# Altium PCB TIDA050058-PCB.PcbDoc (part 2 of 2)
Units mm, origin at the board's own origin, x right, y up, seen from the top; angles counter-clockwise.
Board outline 100 x 60.38 mm, 2 copper layers (Top Layer, Bottom Layer), stack 1.575 mm thick; 72 components, 26 nets, 132 pads, 53 vias.
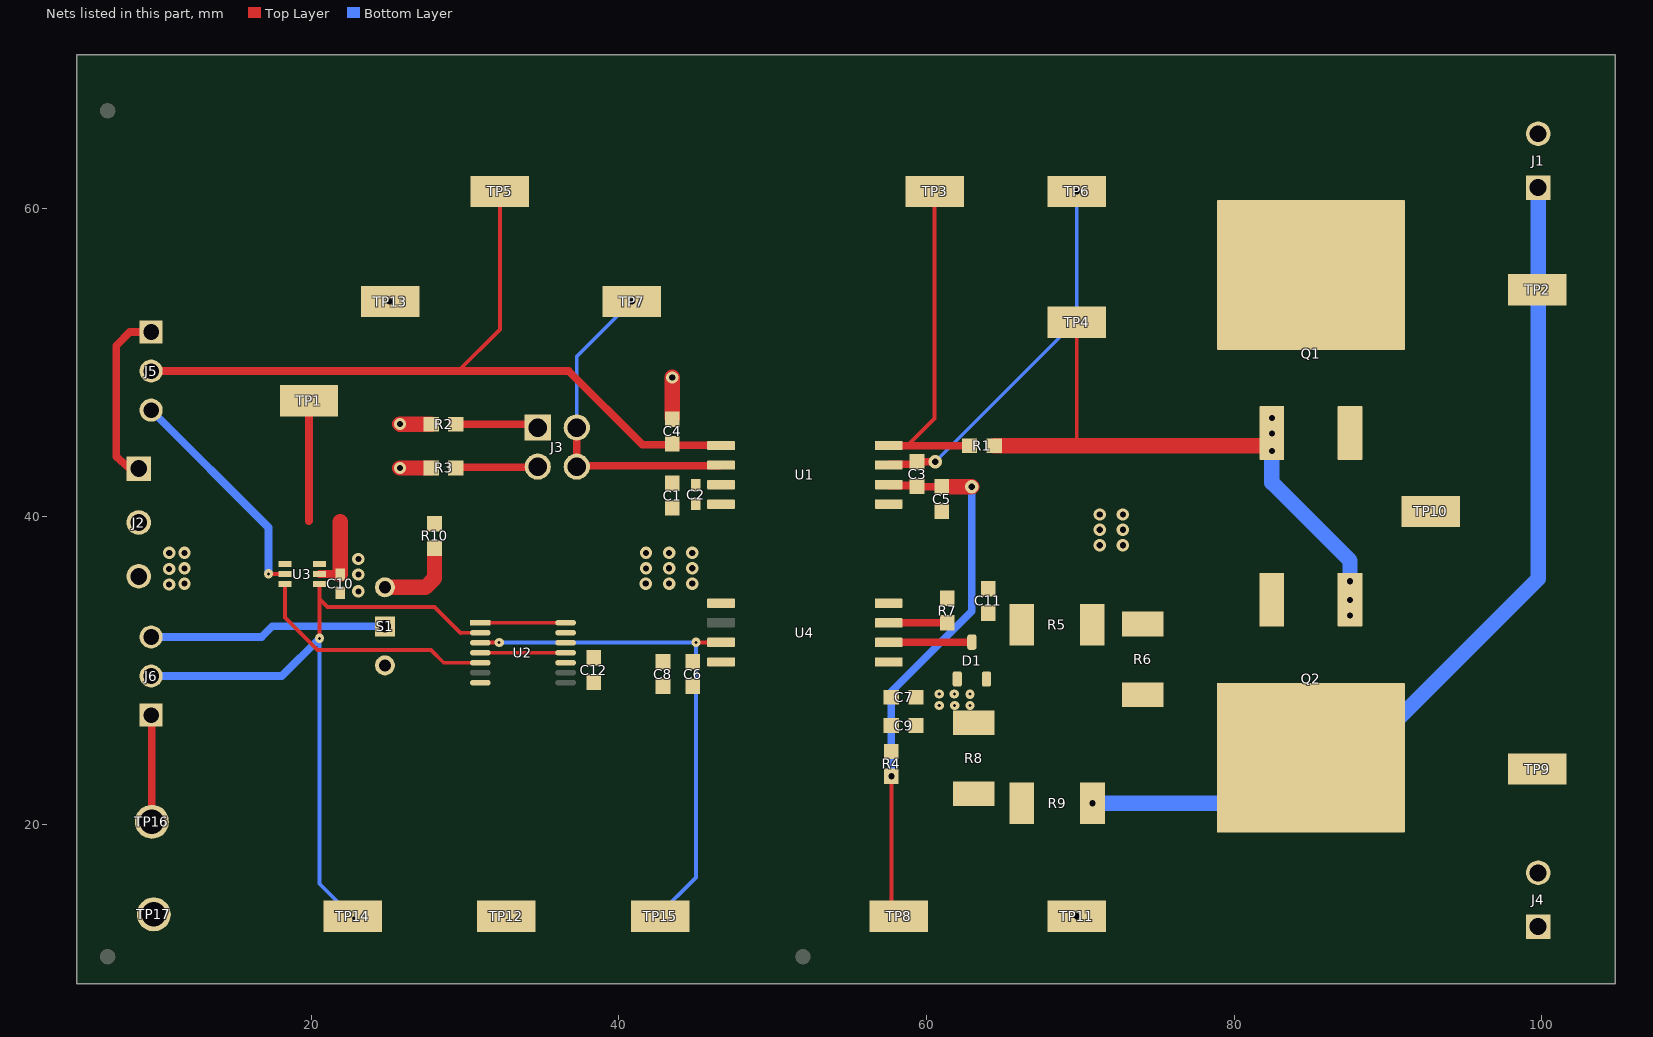
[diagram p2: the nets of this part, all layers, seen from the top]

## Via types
v1: diameter 0.8, hole 0.4, Top Layer to Bottom Layer, tented both sides, 35 vias
v2: diameter 0.61, hole 0.203, Top Layer to Bottom Layer, tented both sides, 12 vias
v3: diameter 0.864, hole 0.406, Top Layer to Bottom Layer, tented both sides, 6 vias

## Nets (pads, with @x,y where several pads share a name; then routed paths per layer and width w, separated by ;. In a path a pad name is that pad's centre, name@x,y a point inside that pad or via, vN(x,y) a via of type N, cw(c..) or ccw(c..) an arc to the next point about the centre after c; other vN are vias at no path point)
EN: C4.1 J5.2 TP5.1 U1.1 | length 51.9
  Top Layer w0.25: 29.568,49.445 32.275,52.152 TP5.1@32.275,61.125
  Top Layer w0.5: J5.2@9.601,49.445 29.568,49.445 36.756,49.445 41.547,44.654 43.49,44.654 43.517,44.627 46.624,44.627 U1.1@46.651,44.6
NetC3_1: C3.1 TP6.1 U1.7 | length 24.5
  Top Layer w0.5: U1.7@57.551,43.33 57.601,43.38 59.226,43.38 C3.1@59.391,43.545 59.394,43.548 60.573,43.548 v3(60.575,43.55)
  Bottom Layer w0.25: v3(60.575,43.55) 69.775,52.75 v3(69.775,61.125)
NetC7_2: C7.2 C9.2 R4.1 U4.1
NetC11_1: C11.1 D1.3 R5.1 U4.2 | length 5.5
  Top Layer w0.5: U4.2@57.551,31.81 62.907,31.81 62.957,31.76 62.957,31.725 D1.3@62.965,31.733
NetJ3_1: J3.1 R2.2 | length 5.4
  Top Layer w0.5: R2.2@29.412,45.995 34.511,45.995 J3.1@34.734,45.773
NetJ3_3: J3.3 R3.2 | length 5.4
  Top Layer w0.5: R3.2@29.412,43.145 29.456,43.189 34.69,43.189 J3.3@34.734,43.233
NetR5_2: R5.2 R6.1
NetR7_2: R7.2 U4.3 | length 3.9
  Top Layer w0.5: U4.3@57.551,33.08 57.554,33.078 61.447,33.078 R7.2@61.45,33.075
NetR8_2: R8.2 R9.1
NetR10_2: R10.2 S1.2 | length 5.4
  Top Layer w1: S1.2@24.8,35.39 27.439,35.39 28.025,35.976 R10.2@28.025,37.925
NetU2_5: U2.5 U3.6 | length 16.1
  Top Layer w0.25: U3.6@18.3,35.6 18.3,33.427 20.423,31.305 27.803,31.305 28.624,30.484 U2.5@31,30.484
OUT2_CLK: TP15.1 U2.3 U4.7 | length 34.5
  Top Layer w0.25: U2.3@31,31.784 31.006,31.791 32.219,31.791 v2(32.225,31.797) ; v2(45.025,31.81) U4.7@46.651,31.81
  Bottom Layer w0.25: v2(32.225,31.797) 32.232,31.803 v2@45.018,31.803 ; v2(42.494,14) 45.013,16.519 45.013,31.798 v2@45.018,31.803 ; v2(45.025,31.81) v2@45.018,31.803
PXFR: J3.2 J3.4 TP7.1 U1.2 | length 21.6
  Top Layer w0.5: J3.2@37.274,45.773 J3.4@37.274,43.233 37.322,43.281 46.603,43.281 U1.2@46.651,43.33
  Bottom Layer w0.25: J3.2@37.274,45.773 37.274,50.393 v3(40.847,53.966)
SEL: J6.2 TP14.1 U2.2 U3.1 | length 46
  Top Layer w0.25: v2(20.55,32.068) 20.55,34.64 ; U3.1@20.55,35.6 20.55,34.64 ; U2.2@31,32.434 30.995,32.43 29.73,32.43 29.725,32.425 28.035,34.115 21.075,34.115 20.55,34.64
  Bottom Layer w0.25: v2(20.55,32.068) 20.55,16.114 v2(22.775,13.889)
  Bottom Layer w0.5: J6.2@9.601,29.62 18.102,29.62 v2(20.55,32.068)
SW1: J1.1 J1.2 Q1.4 R9.2 TP2.1 | length 60.5
  Bottom Layer w1: v3(70.8,21.35) 85.193,21.35 99.775,35.932 J1.1@99.775,61.375
SW2: J4.1 J4.2 Q2.4 R6.2 TP9.1
SWITCH_SEL: J6.3 S1.1 | length 15.5
  Bottom Layer w0.5: J6.3@9.601,32.16 16.791,32.16 17.481,32.85 S1.1@24.8,32.85
USER_EN: J2.1 J5.1 | length 11.7
  Top Layer w0.5: J2.1@8.185,43.142 7.326,43.878 7.326,51.095 8.216,51.985 J5.1@9.601,51.985 ; J2.1@8.26,43.145 J2.1@8.985,43.145
USER_SEL: J6.1 TP16.1 | length 7
  Top Layer w0.5: J6.1@9.601,27.08 9.651,27.03 TP16.1@9.651,20.145
VDDM: C3.2 C5.1 R4.2 TP8.1 U1.6 | length 35.8
  Top Layer w0.25: v3(57.725,23.112) 57.725,14.469 TP8.1@58.194,14
  Top Layer w0.5: U1.6@57.551,42.06 57.601,42.01 59.326,42.01 C3.2@59.391,41.945 59.406,41.93 60.967,41.93 C5.1@60.982,41.916
  Top Layer w1: C5.1@60.982,41.916 62.943,41.916 v3(62.957,41.93)
  Bottom Layer w0.5: v3(57.725,23.112) 57.725,28.59 62.957,33.822 v3(62.957,41.93)
VDDP: C1.1 C2.1 C6.1 C8.1 C10.1 C12.1 J2.2 R10.1 TP1.1 U1.3 U2.1 U2.4 U2.10 U2.11 U2.12 U2.13 U2.14 U3.2 U4.8 | length 23.7
  Top Layer w0.25: U2.4@31,31.134 U2.11@36.55,31.134 ; U2.1@31,33.084 U2.14@36.55,33.084
  Top Layer w0.5: 19.857,39.703 19.864,39.711 TP1.1@19.864,47.516 ; U3.2@20.55,36.25 21.87,36.25 C10.1@21.895,36.225
  Top Layer w1: C10.1@21.895,36.225 21.895,39.643
VDRV: R1.1 TP3.1 U1.8 | length 22.5
  Top Layer w0.25: 58.775,44.6 60.532,46.357 TP3.1@60.532,61.125 ; 59.325,44.6 59.326,44.601
  Top Layer w0.5: U1.8@57.551,44.6 58.775,44.6 59.325,44.6 R1.1@62.801,44.6
VDRV1: Q1.1 Q2.1 R1.2 TP4.1 | length 41.2
  Top Layer w0.25: 69.775,44.6 TP4.1@69.775,52.625 ; 71.584,44.59 71.585,44.591
  Top Layer w1: R1.2@64.401,44.6 64.411,44.59 71.584,44.59 72.509,44.59 82.17,44.59 Q1.1@82.47,44.89
  Bottom Layer w1: v1(82.46,46.39) v1(82.46,45.39) 82.46,42.195 87.54,37.115 v1(87.54,33.561)
  other v1: 87.54,34.572 87.54,35.785 82.46,44.258
VSSP: C1.2 C2.2 C4.2 C6.2 C8.2 C10.2 C12.2 J2.3 R2.1 R3.1 S1.3 TP12.1 TP13.1 TP17.1 U1.4 U2.7 U3.3 U3.4 U4.5 | length 6.7
  Top Layer w1: v1(25.775,43.145) R3.1@27.812,43.145 ; v1(25.775,46) 25.78,45.995 R2.1@27.812,45.995 ; v1(43.476,49.032) 43.49,49.018 C4.2@43.49,46.395
  other v1: 23.075,35.125 10.771,35.575 11.775,35.625 41.76,35.625 43.278,35.625 44.775,35.625 23.075,36.225 10.771,36.575 11.775,36.619 41.775,36.619 43.275,36.625 44.775,36.625 23.075,37.225 10.775,37.625 11.775,37.625 41.775,37.625 43.275,37.625 44.775,37.625 25.097,53.966
VSSS: C5.2 C7.1 C9.1 C11.2 D1.1 D1.2 Q1.3 Q2.3 R7.1 R8.1 TP10.1 TP11.1 U1.5 U4.4
  other v1: 69.775,14 71.275,38.125 72.775,38.125 71.275,39.125 72.775,39.125 71.275,40.125 72.775,40.125
  other v2: 60.84,27.708 61.84,27.708 62.84,27.708 60.84,28.45 61.82,28.45 62.84,28.443
ZCD_EN: J5.3 U3.5 | length 14.9
  Top Layer w0.25: v2(17.233,36.26) 17.238,36.255 18.295,36.255 U3.5@18.3,36.25
  Bottom Layer w0.5: J5.3@9.601,46.905 17.233,39.274 v2(17.233,36.26)
pads on no net: FID1.1 FID2.1 FID3.1 SH-J1.0 SH-J2.0 SH-J3.0 U2.6 U2.8 U2.9 U4.6

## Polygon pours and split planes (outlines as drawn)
NetR8_2 on Top Layer "TOP_LAYER_NETR8_2_P066" (solid, remove dead copper, pour order 66): 61.732,22.775 61.732,21.175 62.907,20 67,20 67,22.8 61.757,22.8
SW2 on Top Layer "Top Layer-ZCS_SW2" (solid, remove dead copper, pour order 65): 78.9,25.741 78.9,14.285 81.875,11.31 100.463,11.298 101.775,12.858 101.775,27.56 99.755,29.19 79.8,29.19 72.735,29.19 72.725,29.2 72.725,27.6 73.573,26.752 77.889,26.752
NetR5_2 on Top Layer "TOP_LAYER_NETR5_2_P063" (solid, remove dead copper, pour order 63): 69.991,34.3 69.991,31.6 71.591,31.6 72.191,32.2 75.425,32.2 75.425,34.3
VSSP on Top Layer "TOP_LAYER_VSSP_P061" (solid, remove dead copper, pour order 61): 6.275,37.425 6.275,14.625 8.775,12.125 45.775,12.125 47.525,13.875 47.525,41.499 16.791,41.499 12.565,38.539 7.389,38.539
NetC11_1 on Top Layer "TOP_LAYER_NETC11_1_P060" (solid, remove dead copper, pour order 60): 62.657,32.351 63.55,32.351 63.55,34.2 64.855,34.2 65.391,34.3 67,34.3 67,31.6 64.048,31.6 63.875,31.369 62.657,31.369
VDDP on Top Layer "TOP_LAYER_VDDP_P012" (solid, remove dead copper, pour order 12): 34.844,39.031 35.775,38.101 35.775,30.45 35.934,30.291 40.757,30.291 41.025,30.023 45.419,30.023 45.651,30.255 47.536,30.255 47.536,30.811 47.525,30.823 45.569,30.823 45.342,31.05 40.759,31.05 40.025,31.784 40.025,41.125 40.52,41.62 45.301,41.62 45.456,41.775 47.189,41.775 47.189,42.36 45.954,42.36 45.669,42.645 40.319,42.645 38.049,40.375 8.725,40.375 8.725,39.031
NetC7_2 on Top Layer "TOP_LAYER_NETC7_2_P011" (solid, remove dead copper, pour order 11): 58.275,24.099 58.275,29.006 58.475,29.206 58.475,30.84 56.654,30.84 56.654,30.806 56.654,24.099
VSSS on Top Layer "TOP_LAYER_VSSS_P009" (solid, remove dead copper, pour order 9): 58.825,28.725 58.825,25.925 59.075,25.675 64.407,25.675 64.775,25.925 64.775,28.85 64.314,29.133 64.314,29.988 61.699,29.988 61.699,29.133 61.36,28.85 58.975,28.85
VSSS on Top Layer "TOP_LAYER_VSSS_P004" (solid, remove dead copper, pour order 4): 56.702,34.05 58.4,34.05 62.175,34.05 63.075,34.8 64.75,34.8 67.542,37.55 80.875,37.55 81.615,36.81 81.615,32.846 83.159,32.846 83.26,32.947 83.259,36.834 83.975,37.55 93.875,37.55 94.725,38.4 94.725,42.075 89.632,47.168 84.064,47.168 84.064,43.539 81.615,41.09 56.702,41.09 56.651,41.039 56.651,34.101
SW1 on Top Layer "TOP_LAYER_SW1_P000" (solid, remove dead copper, pour order 0): 78.85,50.77 89.947,50.77 90.011,50.706 100.506,50.706 101.775,51.975 101.775,64.775 100.66,65.89 80.6,65.89 78.85,63.5
VSSP on Bottom Layer "BOTTOM_LAYER_VSSP_P007" (solid, remove dead copper, pour order 7): 10.025,64.625 6.175,60.775 6.175,14.725 8.775,12.125 45.775,12.125 47.525,13.875 47.525,61.875 44.775,64.625
VSSS on Bottom Layer "BOTTOM_LAYER_VSSS_P005" (solid, remove dead copper, pour order 5): 56.675,13.875 58.425,12.125 65.468,12.125 71.775,12.125 71.775,15.25 66.78,15.22 65.285,17.025 65.285,28.038 73.325,36.077 73.325,62.127 70.975,64.477 59.265,64.465 56.675,61.875

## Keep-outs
Keep-Out Layer:
  text ".Layer_Name" at 19.431,-12.181 h1.52

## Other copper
Top Layer:
  text ".Layer_Name" at 19.431,-12.181 h1.52
Bottom Layer:
  text ".Layer_Name" at 19.431,-12.181 h1.52

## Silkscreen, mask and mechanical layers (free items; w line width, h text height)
Top Overlay:
  lines w0.254: 17.154,27.498 18.154,26.498 38.752,26.498 39.752,27.498 39.752,39.914 38.752,40.914 18.154,40.914 17.154,39.914 17.154,27.498 ; 40.757,19.5 41.757,18.5 76.4,18.5 77.4,19.5 77.4,36.375 76.4,37.375 41.757,37.375 40.757,36.375 40.757,19.5 ; 40.757,39.325 41.757,38.325 64.6,38.325 65.6,39.325 65.6,48.9 64.6,49.9 41.757,49.9 40.757,48.9 40.757,39.325
  text "EN" at 31.775,63.125 h1.5
  text "VDRV" at 58.775,63.125 h1.5
  text "VDDH" at 68.275,63.125 h1.5
  text "SW1" at 92.375,60.443 h1.5
  text "Max Loading Conditions: / V Load = 500Vdc/350Vrms / Frequency = 50/60Hz / I load = 4A" at 74.375,58.625 h0.9
  text "Recommended Conditions: / - Three Wire Mode: /      EN: 5-Vdc /      VDDP: 5-Vdc" at 9.675,58.125 h1.5
  text "VSSP" at 23.387,55.811 h1.5
  text "PXFR" at 39.125,55.775 h1.5
  text "SW1" at 94.075,54.561 h1.5
  text "VG" at 68.775,54.543 h1.5
  text "USER_EN" at 11.148,51.704 h1
  text "Isolated Switch Driver" at 46.709,50.318 h1.5
  text "VDDP" at 18.17,49.482 h1.5
  text "EN" at 11.173,49.092 h1
  text "PXFR #1" at 26.877,47.048 h1
  text "ZCD_EN" at 11.148,46.624 h1
  text "TPSI3050-Q1" at 48.048,46.149 h1.5
  text "PXFR #2" at 26.877,44.207 h1
  text "USER_EN" at 13,42.614 h1.5
  text "VSSS" at 90.825,42.318 h1.5
  text "CAUTION" at 69.973,39.643 h1.5
  text "VDDP" at 12.941,39.193 h1.5
  text "HOT SURFACE" at 67.773,38.343 h1.5
  text "VSSP" at 12.941,36.058 h1.5
  text "ON" at 26.514,35.137 h1
  text "SWITCH_SEL" at 11.098,31.949 h1
  text "DANGER" at 95.475,31.543 h1.5
  text "HIGH VOLTAGE" at 93.275,30.243 h1.5
  text "OFF" at 26.375,30.012 h1
  text "SEL" at 11.098,29.447 h1
  text "USER_SEL" at 11.125,26.802 h1
  text "Zero Cross Switching" at 21.144,25.208 h1.5
  text "SW2" at 93.875,23.243 h1.5
  text "USER_SEL" at 11.775,19.84 h1.5
  text "Zero Cross Detection" at 41.935,19.017 h1.5
  text "SEL" at 21.733,16.143 h1.5
  text "VSSP" at 31.233,16.16 h1.5
  text "OUT2-CLK" at 39.233,16.143 h1.5
  text "VSSS" at 67.828,16.143 h1.5
  text "VDDM" at 56.294,16.125 h1.5
  text "SW2" at 92.375,14.643 h1.5
  text "VSSP" at 11.9,13.318 h1.5
  text ".Layer_Name" at 19.431,-12.181 h1.52
Bottom Overlay:
  text ".Layer_Name" at 19.431,-12.181 h1.52
Top Paste:
  text ".Layer_Name" at 19.431,-12.181 h1.52
Bottom Paste:
  text ".Layer_Name" at 19.431,-12.181 h1.52
Top Solder:
  text ".Layer_Name" at 19.431,-12.181 h1.52
  text ".Layer_Name" at 19.431,-12.181 h1.52
Bottom Solder:
  text ".Layer_Name" at 19.431,-12.181 h1.52
Drill Guide:
  text ".Layer_Name" at 19.431,-12.181 h1.52
M1 Board Outline:
  the board outline again, w0.254
  text ".Layer_Name" at 19.431,-12.181 h1.52
M2 Board Dimensions:
  rectangle: 4.775,2.64 7.95,5.815
  rectangle: 7.95,-0.535 17.475,2.64
  lines w0.178: 4.775,2.64 30.175,2.64 ; 7.95,-0.535 7.95,5.815 ; 11.125,-0.535 11.125,5.815 ; 17.475,-0.535 17.475,5.815 ; 23.825,-0.535 23.825,5.815 ; 4.775,-0.535 30.175,-0.535 30.175,5.815 4.775,5.815 4.775,-0.535
  text ".Layer_Name" at 19.431,-12.181 h1.52
M3 3D STEP Top:
  text ".Layer_Name" at 19.431,-12.181 h1.52
M4 3D STEP Bottom:
  text ".Layer_Name" at 19.431,-12.181 h1.52
M5 Assembly Top:
  lines w0.254: -2.642,-14.001 164.998,-14.001 ; -2.642,-8.837 165.049,-8.837 ; -2.642,-3.672 -2.642,-19.166 99.085,-19.166 165.049,-19.166 165.049,-3.672 -2.629,-3.672 -2.629,-19.166 37.389,-19.166 ; 59.969,-19.166 59.969,-3.672 ; 92.151,-8.837 92.151,-3.672 ; 113.487,-8.837 113.487,-3.672 ; 129.286,-19.331 129.286,-14.179
  text "COMPONENTS MARKED 'DNP' SHOULD NOT BE POPULATED." at 34.074,1.535 h1.52
  text "ASSEMBLY VARIANT:" at 34.061,-1.399 h1.52
  text ".VariantName" at 60.376,-1.399 h1.52
  text "PCB VIEWED FROM TOP SIDE" at -1.029,-7.029 h1.52
  text "BOARD #:" at 61.874,-7.029 h1.52
  text ".PRJ_Number" at 75.73,-7.029 h1.52
  text "REV:" at 97.18,-7.029 h1.52
  text ".PCB_Rev" at 104.584,-7.029 h1.52
  text "SVN REV:" at 118.465,-7.029 h1.52
  text ".VersionControl_RevNumber" at 131.318,-7.029 h1.52
  text "TID #:" at 61.874,-12.194 h1.52
  text ".TID" at 75.73,-12.194 h1.52
  text "PLOT NAME =" at -1.029,-17.409 h1.52
  text ".plot_File_Name" at 19.431,-17.409 h1.52
  text "GENERATED    :" at 61.925,-17.409 h1.52
  text ".Print_Date" at 84.01,-17.409 h1.52
  text ".Print_Time" at 102.527,-17.409 h1.52
  text "TEXAS INSTRUMENTS" at 134.645,-17.409 h1.52
M6 Assembly Bottom:
  lines w0.254: -2.655,-8.849 165.036,-8.849 ; -2.604,-14.014 165.036,-14.014 ; 33.109,-19.344 33.109,-14.192 ; 48.907,-8.849 48.907,-3.685 ; 70.243,-8.849 70.243,-3.685 ; 102.425,-19.179 102.425,-3.685 ; 125.006,-19.179 165.024,-19.179 165.024,-3.685 -2.655,-3.685 -2.655,-19.179 63.309,-19.179 165.036,-19.179 165.036,-3.685
  text "COMPONENTS MARKED 'DNP' SHOULD NOT BE POPULATED." at 159.766,1.548 h1.52
  text ".VariantName" at 133.248,-1.399 h1.52
  text "ASSEMBLY VARIANT:" at 159.639,-1.399 h1.52
  text ".VersionControl_RevNumber" at 31.077,-7.042 h1.52
  text "SVN REV:" at 43.929,-7.042 h1.52
  text ".PCB_Rev" at 57.81,-7.042 h1.52
  text "REV:" at 65.214,-7.042 h1.52
  text ".PRJ_Number" at 86.665,-7.042 h1.52
  text "BOARD #:" at 100.52,-7.042 h1.52
  text "PCB VIEWED FROM BOTTOM SIDE" at 163.423,-7.042 h1.52
  text ".TID" at 86.665,-12.206 h1.52
  text "TID #:" at 100.52,-12.206 h1.52
  text "TEXAS INSTRUMENTS" at 27.749,-17.422 h1.52
  text ".Print_Time" at 59.868,-17.422 h1.52
  text ".Print_Date" at 78.384,-17.422 h1.52
  text "GENERATED    :" at 100.469,-17.422 h1.52
  text ".plot_File_Name" at 142.964,-17.422 h1.52
  text "PLOT NAME =" at 163.423,-17.422 h1.52
M9 Title Sheet:
  drawing of 57 lines, arcs and shapes, not listed
  text "1" at 23.567,213.752 h1.78
  text "2" at 86.957,213.752 h1.78
  text "3" at 150.186,213.752 h1.78
  text "4" at 213.855,213.752 h1.78
  text "5" at 277.33,213.752 h1.78
  text "6" at 340.957,213.752 h1.78
  text "A" at -5.804,184.72 h1.78
  text "A" at 370.116,184.72 h1.78
  text "B" at -5.804,124.268 h1.78
  text "B" at 370.116,124.268 h1.78
  text "C" at -5.804,63.943 h1.78
  text "C" at 370.116,63.943 h1.78
  text "PROJECT TITLE:" at 292.9,16.673 h1.14
  text ".PRJ_Title" at 294.17,13.287 h1.78
  text "DESIGNED FOR:" at 292.9,9.028 h1.14
  text ".PRJ_Customer" at 294.17,5.472 h1.78
  text "D" at -5.804,3.745 h1.78
  text "D" at 370.116,3.745 h1.78
  text "FILE NAME:" at 292.9,1.408 h1.14
  text ".PCB_File_Name_No_Path" at 294.17,-1.64 h1.78
  text "Texas Instruments (TI) and/or its licensors do not warrant the accuracy or completeness of this specification" at 166.675,-5.751 h1.14
  text "ENGINEER:" at 292.9,-5.958 h1.14
  text "LAYOUT BY:" at 331.127,-5.958 h1.14
  text "or any information contained therein. TI and/or its licensors do not warrant that this design will meet" at 165.532,-8.612 h1.14
  text ".PRJ_Engineer" at 294.17,-9.895 h1.78
  text ".PCB_Layout" at 332.41,-9.895 h1.78
  text "the specifications, will be suitable for your application or fit for any particular purpose, or will operate in" at 165.532,-11.474 h1.14
  text ".Layer_Name" at 19.431,-12.181 h1.52
  text "ALTIUM DESIGNER VERSION:" at 331.127,-13.832 h1.14
  text "an implementation. TI and/or its licensors do not warrant that the design is production worthy. You should" at 165.532,-14.336 h1.14
  text "completely validate and test your design implementation to confirm the system functionality for your application." at 166.675,-17.197 h1.14
  text ".print_Scale" at 294.17,-17.218 h1.78
  text ".Application_BuildNumber" at 332.41,-17.218 h1.78
  text "1" at 23.567,-22.468 h1.78
  text "2" at 86.957,-22.468 h1.78
  text "3" at 150.186,-22.468 h1.78
  text "4" at 213.855,-22.468 h1.78
  text "5" at 277.33,-22.468 h1.78
  text "6" at 340.957,-22.468 h1.78
M10 Fab Notes:
  drawing of 189 lines, arcs and shapes, not listed
  text "DESIGN INFORMATION" at 319.278,171.072 h1.52
  text "MIN. TRACK WIDTH:" at 302.906,167.716 h1.52
  text "8" at 330.751,167.716 h1.52
  text "MIL" at 334.682,167.716 h1.52
  text "7.874" at 326.525,164.625 h1.52
  text "MIN. CLEARANCE:" at 302.906,164.563 h1.52
  text "MIL" at 334.682,164.563 h1.52
  text "MIN. VIA PAD SIZE:" at 302.906,161.41 h1.52
  text "24" at 329.989,161.41 h1.52
  text "MIL" at 334.682,161.41 h1.52
  text "0.05mm (2MIL)" at 320.559,158.111 h1.52
  text "MINIMUM ANNULAR RING" at 294.544,157.902 h1.52
  text "EXTERNAL" at 338.543,157.902 h1.52
  text "PER" at 299.624,155.105 h1.52
  text "IPC-D-275 CLASS 2 LEVEL C" at 305.212,155.105 h1.52
  text "MIL, HOLES" at 343.013,152.553 h1.52
  text "+/-" at 333.045,152.334 h1.52
  text "+/-" at 354.736,152.334 h1.52
  text "REGISTRATION TOLERANCES:" at 294.544,152.307 h1.52
  text "METAL" at 325.018,152.307 h1.52
  text "5" at 339.654,152.308 h1.52
  text "3" at 360.812,152.308 h1.52
  text "MIL" at 363.765,152.307 h1.52
  text "HOLE SIZE TOLERANCE (UNLESS OTHERWISE SPECIFIED):" at 294.544,149.81 h1.52
  text "+/-" at 354.736,149.737 h1.52
  text "3" at 360.812,149.71 h1.52
  text "MIL" at 363.765,149.71 h1.52
  text "MATERIAL:" at 292.645,146.214 h1.52
  text "FR-4 High Tg" at 317.701,142.949 h1.52
  text "X" at 314.032,142.747 h1.52
  text "FR-408" at 303.338,142.632 h1.52
  text "OTHER" at 341.133,142.632 h1.52
  text "62 MIL (1.6mm) +/-10%" at 311.469,138.999 h1.52
  text "X" at 308.418,138.937 h1.52
  text "THICKNESS:" at 294.544,138.79 h1.52
  text "OTHER" at 344.105,138.79 h1.52
  text "TOLERANCE:" at 294.544,135.277 h1.52
  text "X" at 316.089,135.277 h1.52
  text "ANSI IPC-6012 TYPE 3 CLASS 2" at 320.611,135.277 h1.52
  text "OTHER +/-" at 320.61,131.614 h1.52
  text "BOW & TWIST:" at 294.544,127.927 h1.52
  text "X" at 316.089,127.927 h1.52
  text "ANSI IPC-6012 TYPE 3 CLASS 2" at 320.611,127.927 h1.52
  text "OTHER +/-" at 320.61,124.201 h1.52
  text "DRILLING:" at 292.645,120.883 h1.52
  text "NC_DRILL FILES" at 337.374,118.211 h1.52
  text "REFERENCE:" at 294.544,118.111 h1.52
  text "X" at 311.238,118.109 h1.52
  text "AS SHOWN" at 315.759,118.111 h1.52
  text "X" at 334.123,118.111 h1.52
  text "OTHER" at 344.943,114.498 h1.52
  text "PTH COPPER THICKNESS:" at 294.536,114.408 h1.52
  text "X" at 323.472,114.408 h1.52
  text "20-30 um" at 326.723,114.408 h1.52
  text "BOARD FINISH:" at 292.645,110.659 h1.52
  text "SILKSCREEN:" at 296.587,107.862 h1.52
  text "X" at 320.915,107.862 h1.52
  text "TOP" at 323.887,107.862 h1.52
  text "X" at 333.869,107.862 h1.52
  text "BOTTOM" at 336.866,107.862 h1.52
  text "SILKSCREEN COLOR:" at 296.587,103.92 h1.52
  text "X" at 320.89,103.92 h1.52
  text "WHITE" at 323.887,103.92 h1.52
  text "OTHER" at 336.866,103.92 h1.52
  text "X" at 324.217,100.277 h1.52
  text "GREEN" at 327.214,100.277 h1.52
  text "OTHER" at 342.911,100.277 h1.52
  text "SOLDER RESIST COLOR:" at 296.587,100.102 h1.52
  text "X" at 324.217,96.359 h1.52
  text "MATTE" at 327.214,96.359 h1.52
  text "SEMI-GLOSS" at 342.9,96.342 h1.52
  text "IMMERSION GOLD (ENIG)" at 319.594,91.97 h1.52
  text "ENEPIG" at 353.568,91.787 h1.52
  text "SURFACE FINISH:" at 292.645,91.761 h1.52
  text "X" at 315.073,91.761 h1.52
  text "IMM. TIN/SILVER OR EQUIV" at 301.015,88.274 h1.52
  text "OTHER" at 337.374,88.174 h1.52
  text "ARRAY/PANEL:" at 292.645,84.227 h1.52
  text "CUT AND TRIM PER M1 BOARD OUTLINE" at 319.594,84.018 h1.52
  text "N.C. ROUTE" at 319.594,80.565 h1.52
  text "X" at 337.07,80.565 h1.52
  text "V. SCORE" at 341.591,80.565 h1.52
  text "CERTIFICATION:" at 292.645,77.285 h1.52
  text "MATERIALS AND WORKMANSHIP FOR ALL PCBS" at 311.06,77.285 h1.52
  text "TO MEET OR EXCEED THE REQUIREMENTS OF:" at 311.06,74.896 h1.52
  text "X" at 301.853,71.628 h1.52
  text "ANSI IPC-A-600F CLASS ->" at 305.104,71.628 h1.52
  text "X" at 346.963,71.628 h1.52
  text "2" at 349.757,71.628 h1.52
  text "1" at 341.756,71.59 h1.52
  text "3" at 358.748,71.59 h1.52
  text "X" at 322.477,67.877 h1.52
  text "RoHS" at 325.728,67.877 h1.52
  text "OTHER" at 342.096,67.877 h1.52
  text "PER ORDER" at 352.182,67.877 h1.52
  text "ALL BOARDS MUST MEET OR EXCEED UL94-V0 REQUIREMENTS." at 293.344,63.97 h1.52
  text "PCB MUST BEAR THE UL94V-0 UL REGISTERED MATERIAL ID NUMBER" at 293.344,61.022 h1.52
  text "ADDITIONAL REQUIREMENTS:" at 292.645,56.719 h1.52
  text "MICROSECTION:" at 294.544,53.998 h1.52
  text "YES" at 317.55,53.998 h1.52
  text "REQUIRED" at 339.432,50.332 h1.52
  text "BARE BOARD ELEC. TEST:" at 294.544,50.259 h1.52
  text "NONE" at 327.71,50.259 h1.52
  text "X" at 336.435,50.259 h1.52
  text "PER ORDER" at 354.468,50.259 h1.52
  text "XX MIL VIAS REQUIRE NON-CONDUCTIVE FILL AND PLANARIZE" at 298.815,45.053 h1.5
  text "XX MIL VIAS REQUIRE CONDUCTIVE FILL AND PLANARIZE" at 299.018,42.412 h1.52
  text "OUTER XX MIL TRACES REQUIRE 50 OHM SINGLE-ENDED IMPEDANCE" at 298.993,38.262 h1.47
  text "LAYER 2 & 3 (INNER LAYERS) XX MIL WIDE, XX MIL SPACE / TRACES REQUIRE 100 OHM DIFFERENTIAL IMPEDANCE" at 298.79,32.275 h1.52
  text ".Layer_Name" at 19.431,-12.181 h1.52
M11 Gerber Information:
  lines w0.254: -2.642,-14.001 164.998,-14.001 ; -2.642,-8.837 165.049,-8.837 ; -2.642,-3.672 -2.642,-19.166 99.085,-19.166 165.049,-19.166 165.049,-3.672 -2.629,-3.672 -2.629,-19.166 37.389,-19.166 ; 59.969,-19.166 59.969,-3.672 ; 92.151,-8.837 92.151,-3.672 ; 113.487,-8.837 113.487,-3.672 ; 129.286,-19.331 129.286,-14.179
  text "ALL ARTWORK VIEWED FROM TOP SIDE" at -1.029,-7.029 h1.52
  text "BOARD #:" at 61.874,-7.029 h1.52
  text ".PRJ_Number" at 75.73,-7.029 h1.52
  text "REV:" at 97.18,-7.029 h1.52
  text ".PCB_Rev" at 104.584,-7.029 h1.52
  text "SVN REV:" at 118.465,-7.029 h1.52
  text ".VersionControl_RevNumber" at 131.318,-7.029 h1.52
  text "LAYER NAME =" at -1.029,-12.181 h1.52
  text "TID #:" at 61.874,-12.194 h1.52
  text ".TID" at 75.73,-12.194 h1.52
  text "PLOT NAME =" at -1.029,-17.409 h1.52
  text ".plot_File_Name" at 19.431,-17.409 h1.52
  text "GENERATED    :" at 61.925,-17.409 h1.52
  text ".Print_Date" at 84.01,-17.409 h1.52
  text ".Print_Time" at 102.527,-17.409 h1.52
  text "TEXAS INSTRUMENTS" at 134.645,-17.409 h1.52
M12 Stackup:
  drawing of 191 lines, arcs and shapes, not listed
  text "Layer" at 254.243,209.648 h1.52
  text "Name" at 264.655,209.648 h1.52
  text "Material" at 288.271,209.648 h1.52
  text "Thickness" at 310.109,209.648 h1.52
  text "Constant" at 326.615,209.648 h1.52
  text "Board Layer Stack" at 341.089,209.648 h1.52
  text "Top Overlay" at 264.655,206.6 h1.52
  text "Top Solder" at 264.655,203.552 h1.52
  text "Solder Resist" at 288.271,203.552 h1.52
  text "0.40mil" at 310.109,203.552 h1.52
  text "3.5" at 326.615,203.552 h1.52
  text "1" at 254.243,200.504 h1.52
  text "Top Layer" at 264.655,200.504 h1.52
  text "1.40mil" at 310.109,200.504 h1.52
  text "Dielectric1" at 264.655,197.456 h1.52
  text "FR-4 High Tg" at 288.271,197.456 h1.52
  text "59.20mil" at 310.109,197.456 h1.52
  text "4.8" at 326.615,197.456 h1.52
  text "2" at 254.243,194.408 h1.52
  text "Bottom Layer" at 264.655,194.408 h1.52
  text "1.40mil" at 310.109,194.408 h1.52
  text "Bottom Solder" at 264.655,191.36 h1.52
  text "Solder Resist" at 288.271,191.36 h1.52
  text "0.40mil" at 310.109,191.36 h1.52
  text "3.5" at 326.615,191.36 h1.52
  text "Bottom Overlay" at 264.655,188.312 h1.52
  text ".Layer_Name" at 19.431,-12.181 h1.52
M13 Component Bodies Top:
  text ".Layer_Name" at 19.431,-12.181 h1.52
M14 Component Bodies Bottom:
  text ".Layer_Name" at 19.431,-12.181 h1.52
M15 Courtyards Top:
  text ".Layer_Name" at 19.431,-12.181 h1.52
M16 Courtyards Bottom:
  text ".Layer_Name" at 19.431,-12.181 h1.52
Drill Drawing:
  circle w0.254: c151.831,147.263 r0.702
  lines w0.254: 151.129,124.808 151.48,124.808 151.831,124.457 152.182,124.808 152.533,124.808 152.182,125.159 152.533,125.51 152.182,125.51 151.831,125.861 151.48,125.51 151.129,125.51 151.48,125.159 151.129,124.808 ; 151.129,127.615 151.831,127.966 152.533,127.615 152.182,128.317 152.533,129.018 151.831,128.667 151.129,129.018 151.48,128.317 151.129,127.615 ; 151.129,130.773 152.533,130.773 152.533,132.176 151.129,132.176 151.129,130.773 ; 151.129,135.334 152.533,135.334 151.831,133.93 151.129,135.334 ; 151.129,137.439 151.48,137.439 151.48,137.088 152.182,137.088 152.182,137.439 152.533,137.439 152.533,138.141 152.182,138.141 152.182,138.491 151.48,138.491 151.48,138.141 151.129,138.141 151.129,137.439 ; 151.129,140.246 151.129,140.597 151.48,140.947 151.129,141.298 151.129,141.649 151.48,141.649 151.831,141.298 152.182,141.649 152.533,141.649 152.533,141.298 152.182,140.947 152.533,140.597 152.533,140.246 152.182,140.246 151.831,140.597 151.48,140.246 151.129,140.246 ; 151.129,144.105 151.831,143.403 152.533,144.105 151.831,144.807 151.129,144.105
  lines w0.305: 149.857,123.51 231.937,123.51 ; 149.857,148.772 231.937,148.772 ; 158.439,120.352 158.439,151.929 ; 166.871,120.352 166.871,151.929 ; 183.04,120.352 183.04,151.929 ; 189.622,120.352 189.622,151.929 ; 199.151,120.352 199.151,151.929 ; 217.549,120.352 217.549,151.929 ; 149.857,120.352 231.937,120.352 231.937,151.929 149.857,151.929 149.857,120.352
  text "Symbol" at 151.752,149.719 h1.83
  text "Quantity" at 159.386,149.719 h1.83
  text "Finished Hole Size" at 167.819,149.719 h1.83
  text "Plated" at 183.987,149.719 h1.83
  text "Hole Type" at 190.57,149.719 h1.83
  text "Drill Layer Pair" at 200.099,149.719 h1.83
  text "Hole Tolerance" at 218.497,149.719 h1.83
  text "12" at 159.386,146.561 h1.52
  text "8.00mil (0.203mm)" at 167.819,146.561 h1.52
  text "PTH" at 183.987,146.561 h1.52
  text "Round" at 190.57,146.561 h1.52
  text "Top Layer - Bottom Layer" at 200.099,146.561 h1.52
  text "35" at 159.386,143.403 h1.52
  text "15.75mil (0.400mm)" at 167.819,143.403 h1.52
  text "PTH" at 183.987,143.403 h1.52
  text "Round" at 190.57,143.403 h1.52
  text "Top Layer - Bottom Layer" at 200.099,143.403 h1.52
  text "6" at 159.386,140.246 h1.52
  text "16.00mil (0.406mm)" at 167.819,140.246 h1.52
  text "PTH" at 183.987,140.246 h1.52
  text "Round" at 190.57,140.246 h1.52
  text "Top Layer - Bottom Layer" at 200.099,140.246 h1.52
  text "3" at 159.386,137.088 h1.52
  text "31.50mil (0.800mm)" at 167.819,137.088 h1.52
  text "PTH" at 183.987,137.088 h1.52
  text "Round" at 190.57,137.088 h1.52
  text "Top Layer - Bottom Layer" at 200.099,137.088 h1.52
  text "6" at 159.386,133.93 h1.52
  text "40.00mil (1.016mm)" at 167.819,133.93 h1.52
  text "PTH" at 183.987,133.93 h1.52
  text "Round" at 190.57,133.93 h1.52
  text "Top Layer - Bottom Layer" at 200.099,133.93 h1.52
  text "7" at 159.386,130.773 h1.52
  text "43.31mil (1.100mm)" at 167.819,130.773 h1.52
  text "PTH" at 183.987,130.773 h1.52
  text "Round" at 190.57,130.773 h1.52
  text "Top Layer - Bottom Layer" at 200.099,130.773 h1.52
  text "4" at 159.386,127.615 h1.52
  text "47.24mil (1.200mm)" at 167.819,127.615 h1.52
  text "PTH" at 183.987,127.615 h1.52
  text "Round" at 190.57,127.615 h1.52
  text "Top Layer - Bottom Layer" at 200.099,127.615 h1.52
  text "2" at 159.386,124.457 h1.52
  text "63.00mil (1.600mm)" at 167.819,124.457 h1.52
  text "PTH" at 183.987,124.457 h1.52
  text "Round" at 190.57,124.457 h1.52
  text "Top Layer - Bottom Layer" at 200.099,124.457 h1.52
  text "75 Total" at 159.386,121.299 h1.52
  text ".Layer_Name" at 19.431,-12.181 h1.52
M17 Embedded Cavity:
  text ".Layer_Name" at 19.431,-12.181 h1.52
M18 Embedded Assembly:
  text ".Layer_Name" at 19.431,-12.181 h1.52
M19 Embedded Keepout:
  text ".Layer_Name" at 19.431,-12.181 h1.52

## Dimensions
4.775,-0.535 to 30.175,-0.535 on M2 Board Dimensions
4.775,9.625 to 4.775,70 on M2 Board Dimensions
4.775,9.625 to 104.775,9.625 on M2 Board Dimensions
